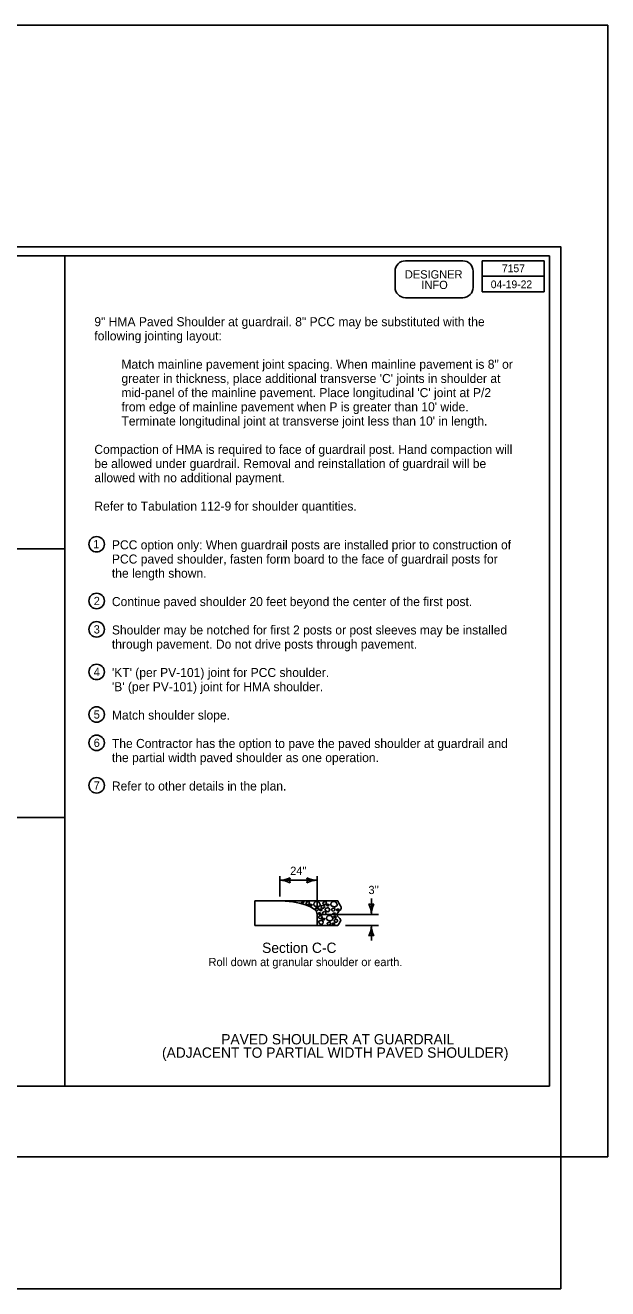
# Model space of a CAD drawing. Extents: x 10038 to 81668, y 7924 to 11018.
# Drawn here: x 12229 to 13359, y 7924 to 10373 of the extents above; entities that cross this region are included whole.
import ezdxf

# ---------------------------------------------------------------- set-up
doc = ezdxf.new("R2010")
doc.units = 0
for name, color, linetype in [('dsnCellElements', 7, 'Continuous'), ('DsnShtMinorGrid01', 7, 'Continuous'), ('DsnShtMinorGrid05', 7, 'Continuous'), ('DsnShtMinorGrid06', 7, 'Continuous'), ('DsnShtMinorGrid07', 7, 'Continuous'), ('DsnShtMinorGrid08', 7, 'Continuous'), ('DsnShtMinorGrid09', 7, 'Continuous'), ('DsnShtMinorGrid10', 7, 'Continuous'), ('DsnShtMinorGrid11', 7, 'Continuous'), ('DsnShtMinorGrid12', 7, 'Continuous'), ('Level 60', 7, 'Continuous'), ('SheetBorder', 7, 'Continuous')]:
    doc.layers.add(name, color=color, linetype=linetype)

msp = doc.modelspace()

# ---------------------------------------------------------------- linework, layer by layer
at = {"layer": 'dsnCellElements'}
msp.add_lwpolyline([(10037.7, 8180), (13358.6, 8180), (13358.6, 10373.4), (10037.7, 10373.4)], close=True, dxfattribs=at)
at = {"layer": 'DsnShtMinorGrid05'}
for p, q in [((12722.8, 8684.5), (12722.8, 8723.9)), ((12795.3, 8723.9), (12795.3, 8660.4)), ((12722.8, 8715.9), (12795.3, 8715.9)), ((12900.4, 8680.8), (12900.4, 8649.8)), ((12802.1, 8649.8), (12914.2, 8649.8)), ((12850.1, 8628), (12914.2, 8628)), ((12900.4, 8628), (12900.4, 8599.4))]:
    msp.add_line(p, q, dxfattribs=at)
for centre, radius, start, end in [((12722.8, 8758.4), 42.5, 270, 298.0725), ((12758.4, 8715.9), 16.4, 162.2666, 197.7334), ((12759.7, 8715.9), 16.4, 342.2666, 17.7334), ((12795.3, 8758.4), 42.5, 241.9275, 270), ((12722.8, 8673.4), 42.5, 61.9275, 90), ((12795.3, 8673.4), 42.5, 90, 118.0725), ((12900.4, 8685.5), 16.4, 252.2666, 287.7334), ((12857.9, 8649.8), 42.5, 0, 28.0725), ((12942.9, 8649.8), 42.5, 151.9275, 180), ((12857.9, 8628), 42.5, 331.9275, 360), ((12942.9, 8628), 42.5, 180, 208.0725), ((12900.4, 8592.4), 16.4, 72.2666, 107.7334)]:
    msp.add_arc(centre, radius, start, end, dxfattribs=at)
at = {"layer": 'DsnShtMinorGrid06'}
for p, q in [((10150.3, 9926.7), (13246, 9926.7)), ((13246, 9926.7), (13246, 8316.7)), ((10150.3, 8316.7), (13246, 8316.7))]:
    msp.add_line(p, q, dxfattribs=at)
at = {"layer": 'DsnShtMinorGrid07'}
for p, q in [((12717.5, 8676), (12674.4, 8676)), ((12674.4, 8676), (12674.4, 8628)), ((12795.3, 8628), (12795.3, 8649.8)), ((12674.4, 8628), (12795.3, 8628))]:
    msp.add_line(p, q, dxfattribs=at)
msp.add_lwpolyline([(12717.5, 8675.9), (12717.5, 8676)], dxfattribs=at)
msp.add_ellipse((12717.5, 8649.8), major_axis=(77.9, 0), ratio=0.335273, start_param=0, end_param=1.570796, dxfattribs=at)
at = {"layer": 'DsnShtMinorGrid08'}
for points in [[(12767.1, 8671.8), (12767.9, 8671.6), (12768.5, 8671.6), (12770.9, 8674), (12766.9, 8674.8), (12763.4, 8672.7), (12766.2, 8671.9), (12767.1, 8671.8)], [(12773.5, 8672.2), (12773.6, 8672.8), (12773.9, 8672.6), (12778.5, 8675.3), (12780.9, 8672.1), (12778.7, 8668.1), (12773.7, 8669.2), (12773.5, 8671.7), (12773.5, 8672.2)], [(12788.4, 8668.5), (12788.1, 8669), (12788.7, 8668.6), (12790.5, 8675.1), (12798.8, 8675.3), (12801.5, 8668.1), (12801.8, 8667.3), (12797, 8663.5), (12790.3, 8665.7), (12788.7, 8668), (12788.4, 8668.5)], [(12806.4, 8672.2), (12806.5, 8672.8), (12806.8, 8672.6), (12811.4, 8675.3), (12813.8, 8672.1), (12811.7, 8668.1), (12806.6, 8669.2), (12806.4, 8671.7), (12806.4, 8672.2)], [(12821.3, 8668.5), (12821, 8669), (12821.6, 8668.6), (12823.5, 8675.1), (12831.8, 8675.3), (12834.4, 8668.1), (12834.7, 8667.3), (12829.9, 8663.5), (12823.2, 8665.7), (12821.6, 8668), (12821.3, 8668.5)], [(12782.7, 8666.3), (12783.6, 8666.1), (12784.1, 8666.1), (12786.5, 8668.5), (12782.5, 8669.3), (12779, 8667.2), (12781.9, 8666.4), (12782.7, 8666.3)], [(12791.9, 8661), (12791.9, 8661.6), (12792.3, 8661.4), (12796.8, 8664.1), (12799.3, 8660.9), (12797.1, 8656.8), (12792, 8657.9), (12791.8, 8660.4), (12791.9, 8661)], [(12797.3, 8651.3), (12796.9, 8651.8), (12797.2, 8652.2), (12801.5, 8653.5), (12802.8, 8650), (12799.6, 8649.2), (12797.7, 8650.8), (12797.3, 8651.3)], [(12798, 8645.1), (12798.1, 8645.7), (12798.4, 8645.5), (12803, 8648.2), (12805.4, 8645), (12803.3, 8641), (12798.2, 8642), (12798, 8644.5), (12798, 8645.1)], [(12802, 8657), (12802.8, 8656.8), (12803.4, 8656.8), (12805.8, 8659.2), (12801.8, 8660.1), (12798.3, 8657.9), (12801.2, 8657.2), (12802, 8657)], [(12802.9, 8665.1), (12802.9, 8665.7), (12803.3, 8665.5), (12807.9, 8668.2), (12810.3, 8665), (12808.1, 8660.9), (12803, 8662), (12802.9, 8664.5), (12802.9, 8665.1)], [(12805.8, 8653.3), (12805.8, 8653.8), (12806.2, 8653.7), (12810.7, 8656.3), (12813.1, 8653.1), (12811, 8649.1), (12805.9, 8650.2), (12805.7, 8652.7), (12805.8, 8653.3)], [(12811, 8659.1), (12810.4, 8660.2), (12810.6, 8660.6), (12815.1, 8663.5), (12819.2, 8661.7), (12820.2, 8656.3), (12814.1, 8653.6), (12811.6, 8657.9), (12811, 8659.1)], [(12812.9, 8641.4), (12812.6, 8641.9), (12813.2, 8641.5), (12815, 8647.9), (12823.3, 8648.2), (12826, 8641), (12826.3, 8640.2), (12821.5, 8636.4), (12814.8, 8638.6), (12813.2, 8640.9), (12812.9, 8641.4)], [(12815.6, 8666.3), (12816.5, 8666.1), (12817, 8666.1), (12819.4, 8668.5), (12815.4, 8669.3), (12811.9, 8667.2), (12814.8, 8666.4), (12815.6, 8666.3)], [(12823.2, 8659.7), (12823.2, 8660.3), (12823.6, 8660.1), (12828.1, 8662.8), (12830.6, 8659.6), (12828.4, 8655.5), (12823.3, 8656.6), (12823.1, 8659.1), (12823.2, 8659.7)], [(12825.9, 8650.9), (12825.5, 8651.4), (12825.9, 8651.7), (12830.1, 8653.1), (12831.5, 8649.6), (12828.3, 8648.8), (12826.3, 8650.4), (12825.9, 8650.9)], [(12827.2, 8644.8), (12826.8, 8645.3), (12827.2, 8645.7), (12831.5, 8647), (12832.8, 8643.5), (12829.6, 8642.7), (12827.6, 8644.3), (12827.2, 8644.8)], [(12834.9, 8657), (12835.8, 8656.8), (12836.3, 8656.8), (12838.7, 8659.2), (12834.7, 8660.1), (12831.2, 8657.9), (12834.1, 8657.2), (12834.9, 8657)], [(12798.4, 8634.5), (12797.9, 8635.7), (12798, 8636.1), (12802.6, 8639), (12806.6, 8637.1), (12807.7, 8631.8), (12801.5, 8629.1), (12799, 8633.4), (12798.4, 8634.5)], [(12807.2, 8639.1), (12808.1, 8639), (12808.6, 8639), (12811, 8641.4), (12807, 8642.2), (12803.5, 8640), (12806.4, 8639.3), (12807.2, 8639.1)], [(12814.8, 8632.6), (12814.8, 8633.1), (12815.2, 8633), (12819.7, 8635.6), (12822.1, 8632.4), (12820, 8628.4), (12814.9, 8629.5), (12814.7, 8632), (12814.8, 8632.6)], [(12826.5, 8629.9), (12827.4, 8629.7), (12827.9, 8629.7), (12830.3, 8632.1), (12826.3, 8632.9), (12822.8, 8630.8), (12825.7, 8630.1), (12826.5, 8629.9)], [(12828.4, 8638), (12828.4, 8638.6), (12828.8, 8638.4), (12833.3, 8641.1), (12835.7, 8637.9), (12833.6, 8633.8), (12828.5, 8634.9), (12828.3, 8637.4), (12828.4, 8638)]]:
    msp.add_open_spline(points, degree=3, dxfattribs=at)
at = {"layer": 'DsnShtMinorGrid09'}
for centre in [(12367.7, 9367.3), (12367.7, 9257.3), (12367.7, 9202.3), (12367.7, 9119.8), (12367.7, 9037.3), (12367.7, 8982.3), (12367.7, 8899.8)]:
    msp.add_circle(centre, 15, dxfattribs=at)
at = {"layer": 'DsnShtMinorGrid11'}
for p, q in [((12305.9, 8316.7), (12305.9, 9926.7)), ((12305.9, 9358.7), (10150.3, 9358.7)), ((12305.9, 8837.7), (10150.3, 8837.7))]:
    msp.add_line(p, q, dxfattribs=at)
at = {"layer": 'DsnShtMinorGrid12'}
for points in [[(12946.3, 9865.3), (12946.3, 9896.7)], [(12946.3, 9896.7), (12946.3, 9865.3)], [(12966.3, 9916.7), (13077.6, 9916.7)], [(13077.6, 9916.7), (12966.3, 9916.7)], [(13097.6, 9896.7), (13097.6, 9865.3)], [(13097.6, 9865.3), (13097.6, 9896.7)], [(13077.6, 9845.3), (12966.3, 9845.3)], [(12966.3, 9845.3), (13077.6, 9845.3)]]:
    msp.add_lwpolyline(points, dxfattribs=at)
for centre, start, end in [((12966.3, 9896.7), 90, 180), ((12966.3, 9896.7), 90, 180), ((13077.6, 9896.7), 0, 90), ((13077.6, 9896.7), 0, 90), ((12966.3, 9865.3), 180, 270), ((12966.3, 9865.3), 180, 270), ((13077.6, 9865.3), 270, 0), ((13077.6, 9865.3), 270, 0)]:
    msp.add_arc(centre, 20, start, end, dxfattribs=at)
at = {"layer": 'Level 60'}
for p, q in [((13246, 9926.7), (13246, 9926.7)), ((12674.4, 8676), (12674.4, 8628)), ((12674.4, 8676), (12717.5, 8675.9)), ((12717.5, 8675.9), (12835.2, 8675.9)), ((12795.3, 8649.8), (12795.3, 8628)), ((12674.4, 8628), (12795.3, 8628)), ((12795.3, 8628), (12835.2, 8628))]:
    msp.add_line(p, q, dxfattribs=at)
msp.add_lwpolyline([(13235.1, 9916.7), (13235.1, 9856.7), (13115.4, 9856.7), (13115.4, 9916.7), (13235.1, 9916.7), (13235.1, 9886.7), (13115.4, 9886.7)], dxfattribs=at)
msp.add_ellipse((12717.5, 8649.8), major_axis=(77.9, 0), ratio=0.335273, start_param=0, end_param=1.570796, dxfattribs=at)
msp.add_spline([(12835.2, 8675.9), (12836.6, 8672.8), (12838.4, 8669.6), (12840.3, 8666.6), (12841.7, 8663.5), (12841.9, 8661.7), (12841.2, 8660), (12838.3, 8656.5), (12835.2, 8653), (12834.1, 8651.3), (12833.7, 8650.4), (12833.6, 8649.5), (12833.6, 8649.1), (12834, 8647.9), (12835, 8646.3), (12837.9, 8643.1), (12840.4, 8640), (12840.9, 8638.4), (12840.8, 8637.6), (12840.6, 8637.2), (12840.4, 8636.8), (12835.1, 8628)], degree=3, dxfattribs=at)
at = {"layer": 'SheetBorder'}
msp.add_lwpolyline([(10132.5, 9944), (13267.5, 9944), (13267.5, 7924), (10132.5, 7924)], close=True, dxfattribs=at)

# ---------------------------------------------------------------- texts
at = {"layer": 'DsnShtMinorGrid01'}
for s, p in [('7157', (13153.5, 9894.7)), ('04-19-22', (13131.8, 9863.7))]:
    msp.add_text(s, height=15, dxfattribs=at).set_placement(p)
at = {"layer": 'DsnShtMinorGrid05'}
for s, p in [("24''", (12742.9, 8726.2)), ("3'' ", (12894.7, 8689.1))]:
    msp.add_text(s, height=16, dxfattribs=at).set_placement(p)
at = {"layer": 'DsnShtMinorGrid09'}
for s, height, p in [('9" HMA Paved Shoulder at guardrail. 8" PCC may be substituted with the', 17.5, (12363.3, 9790)), ('following jointing layout:', 17.5, (12363.3, 9762.5)), ('Match mainline pavement joint spacing. When mainline pavement is 8" or ', 17.5, (12415.8, 9707.5)), ("greater in thickness, place additional transverse 'C' joints in shoulder at ", 17.5, (12415.8, 9680)), ("mid-panel of the mainline pavement. Place longitudinal 'C' joint at P/2 ", 17.5, (12415.8, 9652.5)), ("from edge of mainline pavement when P is greater than 10' wide. ", 17.5, (12415.8, 9625)), ("Terminate longitudinal joint at transverse joint less than 10' in length.", 17.5, (12415.8, 9597.5)), ('Compaction of HMA is required to face of guardrail post. Hand compaction will ', 17.5, (12363.3, 9542.5)), ('be allowed under guardrail. Removal and reinstallation of guardrail will be ', 17.5, (12363.3, 9515)), ('allowed with no additional payment.', 17.5, (12363.3, 9487.5)), ('Refer to Tabulation 112-9 for shoulder quantities.', 17.5, (12363.3, 9432.5)), ('1', 16, (12360.9, 9359.3)), ('PCC option only: When guardrail posts are installed prior to construction of ', 17.5, (12397.3, 9357.4)), ('PCC paved shoulder, fasten form board to the face of guardrail posts for ', 17.5, (12397.3, 9329.9)), ('the length shown.', 17.5, (12397.3, 9302.4)), ('2', 16, (12362.1, 9249.3)), ('Continue paved shoulder 20 feet beyond the center of the first post.', 17.5, (12397.3, 9247.4)), ('3', 16, (12362, 9194.3)), ('Shoulder may be notched for first 2 posts or post sleeves may be installed ', 17.5, (12397.3, 9192.4)), ('through pavement. Do not drive posts through pavement.', 17.5, (12397.3, 9164.9)), ('4', 16, (12362.1, 9111.8)), ("'KT' (per PV-101) joint for PCC shoulder.", 17.5, (12397.3, 9109.9)), ("'B' (per PV-101) joint for HMA shoulder.", 17.5, (12397.3, 9082.4)), ('5', 16, (12362, 9029.3)), ('Match shoulder slope.', 17.5, (12397.3, 9027.4)), ('6', 16, (12362, 8974.3)), ('The Contractor has the option to pave the paved shoulder at guardrail and ', 17.5, (12397.3, 8972.4)), ('the partial width paved shoulder as one operation.', 17.5, (12397.3, 8944.9)), ('7', 16, (12362, 8891.8)), ('Refer to other details in the plan.', 17.5, (12397.3, 8889.9))]:
    msp.add_text(s, height=height, dxfattribs=at).set_placement(p)
at = {"layer": 'DsnShtMinorGrid10'}
for s, height, p in [('Section C-C', 20, (12688.5, 8575)), ('Roll down at granular shoulder or earth.', 16, (12584.7, 8549.4)), ('PAVED SHOULDER AT GUARDRAIL', 20, (12609.3, 8397.7)), ('(ADJACENT TO PARTIAL WIDTH PAVED SHOULDER)', 20, (12494.4, 8371.8))]:
    msp.add_text(s, height=height, dxfattribs=at).set_placement(p)
at = {"layer": 'DsnShtMinorGrid12'}
for s, p in [('DESIGNER', (12965.3, 9882.5)), ('INFO', (12997.4, 9862.1))]:
    msp.add_text(s, height=16, dxfattribs=at).set_placement(p)

doc.saveas('drawing.dxf')
